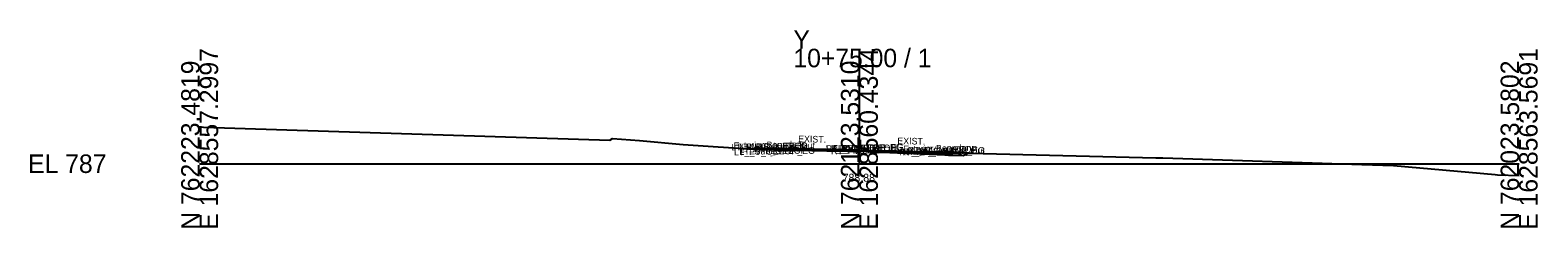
# Model space of a CAD drawing. Extents: x -26 to 203, y -10 to 4017.
# Drawn here: x -25.7 to 202.8, y 1490.3 to 1520.2 of the extents above; entities that cross this region are included whole.
import ezdxf

# ---------------------------------------------------------------- set-up
doc = ezdxf.new("R2010")
doc.units = 0
for name, color, linetype in [('Default', 7, 'Continuous'), ('Exist Cross Section Cell', 7, 'Continuous'), ('Exist XS Center Line Elevation Label', 7, 'Continuous'), ('Exist XS Ground Line', 7, 'Continuous'), ('Prop CMT Pvmt Course 1', 7, 'Continuous'), ('Prop CMT Pvmt Course 1 Wedge', 7, 'Continuous'), ('Prop CMT Pvmt Course 2', 7, 'Continuous'), ('Prop CMT Pvmt Course 2 Wedge', 7, 'Continuous'), ('Prop CMT Pvmt Course 3', 7, 'Continuous'), ('Prop CMT Pvmt Surface', 7, 'Continuous'), ('Prop CMT Pvmt Surface Shoulder', 7, 'Continuous'), ('Prop CMT Pvmt Wedge Surface 1', 7, 'Continuous'), ('Prop CMT Pvmt Wedge Surface 2', 7, 'Continuous'), ('Prop CMT Pvmt Wedge Surface 3', 7, 'Continuous'), ('Prop CMT Shld Paved Course 1', 7, 'Continuous'), ('Prop CMT Shld Paved Course 2', 7, 'Continuous'), ('Prop CMT Slope Grass', 7, 'Continuous'), ('Prop XS SE Text', 7, 'Continuous'), ('Scratch_Level_0', 7, 'Continuous')]:
    doc.layers.add(name, color=color, linetype=linetype)

msp = doc.modelspace()

# ---------------------------------------------------------------- linework, layer by layer
at = {"layer": 'Exist Cross Section Cell'}
for p, q in [((100, 1500), (100, 1517.39)), ((0, 1500), (100, 1500)), ((100, 1500), (200, 1500))]:
    msp.add_line(p, q, dxfattribs=at)
at = {"layer": 'Exist XS Ground Line'}
msp.add_lwpolyline([(0, 1505.57), (0.6, 1505.55), (62.18, 1503.57), (62.56, 1503.79), (66.65, 1503.52), (73.27, 1502.93), (84.73, 1502.15), (98.18, 1501.9), (99.83, 1501.89), (114.18, 1501.28), (115.74, 1501.23), (116.37, 1501.53), (116.75, 1501.6), (144.95, 1500.9), (146.01, 1500.88), (176.16, 1499.88), (180.96, 1499.72), (196.37, 1498.37), (196.7, 1498.34), (200, 1498.24)], dxfattribs=at)
at = {"layer": 'Prop CMT Pvmt Course 1'}
for points in [[(100, 1502.07), (84.92, 1502.37)], [(84.92, 1502.37), (84.92, 1502.25)], [(100, 1502.07), (84.92, 1502.37)], [(84.92, 1502.37), (84.92, 1502.14)], [(84.92, 1502.25), (100, 1501.95)], [(100, 1501.95), (100, 1502.07)], [(100, 1501.82), (100, 1502.07)], [(100, 1502.07), (115, 1501.77)], [(100, 1501.95), (100, 1502.07)], [(100, 1502.07), (115, 1501.77)], [(100, 1501.82), (100, 1502.07)], [(115, 1501.65), (100, 1501.95)], [(115, 1501.77), (115, 1501.65)], [(115, 1501.77), (115, 1501.52)]]:
    msp.add_lwpolyline(points, dxfattribs=at)
at = {"layer": 'Prop CMT Pvmt Course 1 Wedge'}
for points in [[(84.92, 1502.25), (95.82, 1502.03), (99.83, 1501.95), (100, 1501.95)], [(84.92, 1502.14), (84.92, 1502.25)], [(100, 1501.88), (99.83, 1501.89), (95.82, 1501.94), (84.92, 1502.14)], [(100, 1501.95), (100, 1501.88)], [(100, 1501.95), (111.72, 1501.71), (115, 1501.65)], [(100, 1501.88), (100, 1501.95)], [(115, 1501.52), (111.72, 1501.59), (102.6, 1501.77), (100, 1501.88)], [(115, 1501.65), (115, 1501.52)]]:
    msp.add_lwpolyline(points, dxfattribs=at)
at = {"layer": 'Prop CMT Pvmt Course 2'}
msp.add_lwpolyline([(100, 1501.49), (100, 1501.82)], dxfattribs=at)
msp.add_lwpolyline([(100, 1501.49), (100, 1501.82)], dxfattribs=at)
at = {"layer": 'Prop CMT Pvmt Course 2 Wedge'}
for points in [[(102.6, 1501.77), (111.72, 1501.59)], [(111.72, 1501.59), (115, 1501.52)]]:
    msp.add_lwpolyline(points, dxfattribs=at)
at = {"layer": 'Prop CMT Pvmt Course 3'}
msp.add_lwpolyline([(100, 1501.15), (100, 1501.49)], dxfattribs=at)
msp.add_lwpolyline([(100, 1501.15), (100, 1501.49)], dxfattribs=at)
at = {"layer": 'Prop CMT Pvmt Surface'}
for points in [[(100, 1502.07), (84.92, 1502.37)], [(100, 1502.07), (84.92, 1502.37)], [(100, 1502.07), (115, 1501.77)], [(100, 1502.07), (115, 1501.77)]]:
    msp.add_lwpolyline(points, dxfattribs=at)
at = {"layer": 'Prop CMT Pvmt Surface Shoulder'}
for points in [[(84.92, 1502.37), (84.92, 1502.37)], [(115, 1501.77), (115, 1501.77)]]:
    msp.add_lwpolyline(points, dxfattribs=at)
at = {"layer": 'Prop CMT Pvmt Wedge Surface 1'}
for points in [[(84.92, 1502.25), (84.92, 1502.37)], [(100, 1501.95), (84.92, 1502.25)], [(100, 1501.95), (115, 1501.65)], [(115, 1501.65), (115, 1501.77)]]:
    msp.add_lwpolyline(points, dxfattribs=at)
at = {"layer": 'Prop CMT Pvmt Wedge Surface 2'}
for points in [[(100, 1501.82), (100, 1502.07)], [(100, 1501.82), (100, 1502.07)], [(100, 1501.82), (100, 1502.07)], [(100, 1501.82), (100, 1502.07)], [(115, 1501.52), (115, 1501.77)]]:
    msp.add_lwpolyline(points, dxfattribs=at)
at = {"layer": 'Prop CMT Pvmt Wedge Surface 3'}
msp.add_lwpolyline([(100, 1501.49), (100, 1502.07)], dxfattribs=at)
msp.add_lwpolyline([(100, 1501.49), (100, 1502.07)], dxfattribs=at)
msp.add_lwpolyline([(100, 1501.49), (100, 1502.07)], dxfattribs=at)
msp.add_lwpolyline([(100, 1501.49), (100, 1502.07)], dxfattribs=at)
at = {"layer": 'Prop CMT Shld Paved Course 1'}
for points in [[(84.92, 1502.37), (84.69, 1502.15)], [(84.92, 1502.37), (84.92, 1502.37)], [(115, 1501.77), (115, 1501.77)], [(115, 1501.77), (115.26, 1501.52)], [(115, 1501.52), (115, 1501.77)], [(115.26, 1501.52), (115, 1501.52)]]:
    msp.add_lwpolyline(points, dxfattribs=at)
at = {"layer": 'Prop CMT Shld Paved Course 2'}
msp.add_lwpolyline([(115, 1501.52), (115.26, 1501.52), (115.54, 1501.23)], dxfattribs=at)
at = {"layer": 'Prop CMT Slope Grass'}
for p, q in [((84.92, 1502.37), (83.07, 1502.26)), ((115, 1501.77), (117.24, 1501.59))]:
    msp.add_line(p, q, dxfattribs=at)

# ---------------------------------------------------------------- texts
at = {"layer": 'Default'}
msp.add_text('-', height=0.0001, dxfattribs=at).set_placement((0, 1500))
at = {"layer": 'Exist Cross Section Cell'}
for s, p in [('Y', (90, 1517.39)), ('10+75.00 / 1', (90, 1514.59)), ('EL 787', (-26, 1498.6))]:
    msp.add_text(s, height=2.8, dxfattribs=at).set_placement(p)
for s, p in [('N 762223.4819', (0, 1490)), ('E 1628557.2997', (2.8, 1490)), ('N 762123.5310', (100, 1490)), ('E 1628560.4344', (102.8, 1490)), ('N 762023.5802', (200, 1490)), ('E 1628563.5691', (202.8, 1490))]:
    msp.add_text(s, height=2.8, rotation=90, dxfattribs=at).set_placement(p)
at = {"layer": 'Exist XS Center Line Elevation Label'}
msp.add_text('788.88', height=1.2, dxfattribs=at).set_placement((97.46, 1497.28))
at = {"layer": 'Prop XS SE Text'}
for p in [(90.71, 1503.26), (105.75, 1502.96)]:
    msp.add_text('EXIST.', height=1, rotation=358.8542, dxfattribs=at).set_placement(p)
at = {"layer": 'Scratch_Level_0'}
for s, p in [('LT_PV_Sub_Tie_Out', (80.58, 1502)), ('LT_PV_Sub_Tie_Out', (80.58, 1502)), ('Exterior Boundary', (80.96, 1502.24)), ('LT_PV_OEEOP_EG', (81, 1501.26)), ('LT_PV_OEEOP_EG', (81, 1501.26)), ('LT_PV2_OEEOP', (81.79, 1502)), ('LT_PV2_OEEOP', (81.79, 1502)), ('LT_PV3_OEEOP', (81.79, 1501.67)), ('LT_PV3_OEEOP', (81.79, 1501.67)), ('LT_Sub_OEEOP', (81.82, 1501.33)), ('LT_Sub_OEEOP', (81.82, 1501.33)), ('LT_PV1_OEEOP', (81.91, 1502.13)), ('LT_PV1_OEEOP', (81.91, 1502.13)), ('LT_PV2_OEOT', (82.04, 1502.01)), ('LT_PV2_OEOT', (82.04, 1502.01)), ('LT_PV3_OEOT', (82.04, 1501.68)), ('LT_PV3_OEOT', (82.04, 1501.68)), ('LT_Sub_OEOT', (82.06, 1501.34)), ('LT_Sub_OEOT', (82.06, 1501.34)), ('LT_PV1_OEOT', (82.16, 1502.26)), ('LT_PV1_OEOT', (82.16, 1502.26)), ('RT_PV_IEEOP_EG', (94.92, 1501.78)), ('RT_PV_IEEOP_EG', (94.92, 1501.78)), ('LT_PV_IEEOP_EG', (94.98, 1501.78)), ('LT_PV_IEEOP_EG', (94.98, 1501.78)), ('RT_PV2_IEEOP', (95.71, 1501.73)), ('RT_PV2_IEEOP', (95.71, 1501.73)), ('RT_PV3_IEEOP', (95.71, 1501.4)), ('RT_PV3_IEEOP', (95.71, 1501.4)), ('LT_PV2_IEEOP', (95.77, 1501.74)), ('LT_PV2_IEEOP', (95.77, 1501.74)), ('LT_PV3_IEEOP', (95.77, 1501.4)), ('LT_PV3_IEEOP', (95.77, 1501.4)), ('RT_PV1_IEEOP', (95.83, 1501.86)), ('RT_PV1_IEEOP', (95.83, 1501.86)), ('LT_PV1_IEEOP', (95.89, 1501.86)), ('LT_PV1_IEEOP', (95.89, 1501.86)), ('PV2_PGL', (97.35, 1501.77)), ('PV2_PGL', (97.35, 1501.77)), ('PV1_PGL', (97.47, 1502.02)), ('PV1_PGL', (97.47, 1502.02)), ('RT_PV_Sub_Tie_Out', (106.09, 1501.26)), ('RT_PV_Sub_Tie_Out', (106.09, 1501.26)), ('RT_PV_OEEOP_EG', (106.54, 1501.27)), ('RT_PV_OEEOP_EG', (106.54, 1501.27)), ('Exterior Boundary', (106.66, 1501.72)), ('RT_PV2_OEEOP', (107.33, 1501.49)), ('RT_PV2_OEEOP', (107.33, 1501.49)), ('RT_PV3_OEEOP', (107.33, 1501.15)), ('RT_PV3_OEEOP', (107.33, 1501.15)), ('RT_Sub_OEEOP', (107.36, 1500.82)), ('RT_Sub_OEEOP', (107.36, 1500.82)), ('RT_PV1_OEEOP', (107.45, 1501.61)), ('RT_PV1_OEEOP', (107.45, 1501.61)), ('RT_PV2_OEOT', (107.69, 1501.49)), ('RT_PV2_OEOT', (107.69, 1501.49)), ('RT_PV3_OEOT', (107.69, 1501.16)), ('RT_PV3_OEOT', (107.69, 1501.16)), ('RT_Sub_OEOT', (107.71, 1500.83)), ('RT_Sub_OEOT', (107.71, 1500.83)), ('RT_PV1_OEOT', (107.81, 1501.75)), ('RT_PV1_OEOT', (107.81, 1501.75))]:
    msp.add_text(s, height=1, rotation=1.1458, dxfattribs=at).set_placement(p)

doc.saveas('drawing.dxf')
